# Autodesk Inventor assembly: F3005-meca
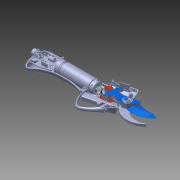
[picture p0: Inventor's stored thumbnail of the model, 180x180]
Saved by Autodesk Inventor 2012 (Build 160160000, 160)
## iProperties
Created: 2014-12
Part Number: F3005-meca
Document SubType Name: Assembly
Designer: Bruno
Author: Bruno
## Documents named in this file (6)
- F:\Systèmes\secateur-hydrogene-Pragma\Documentation\Dossier technique Infaco F3005\Solidworks\Composants importés\F3005-meca.iam
- F:\Systèmes\secateur-hydrogene-Pragma\Documentation\Dossier technique Infaco F3005\Solidworks\Composants importés\F3005-bati.iam
- F:\Systèmes\secateur-hydrogene-Pragma\Documentation\Dossier technique Infaco F3005\Solidworks\Composants importés\F3005\Gachette.ipt
- F:\Systèmes\secateur-hydrogene-Pragma\Documentation\Dossier technique Infaco F3005\Solidworks\Composants importés\F3005-lame-mobile.iam
- F:\Systèmes\secateur-hydrogene-Pragma\Documentation\Dossier technique Infaco F3005\Solidworks\Composants importés\F3005--pignon-intermédiaire.iam
- F:\Systèmes\secateur-hydrogene-Pragma\Documentation\Dossier technique Infaco F3005\Solidworks\Composants importés\F3005-arbre-moteur.iam
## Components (5 placed, 5 different names)
1. F3005-bati:1 [sub-assembly] — Placage:1, Placage:2, Logement:1, Placage:3, Placage:4, Placage:5, Placage:6
2. Gachette:1 — Placage:1, Placage:2
3. F3005-lame-mobile:1 [sub-assembly] — Logement:1
4. F3005--pignon-intermédiaire:1 [sub-assembly] — Placage:3, Placage:4
5. F3005-arbre-moteur:1 [sub-assembly] — Placage:5, Placage:6
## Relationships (7: Mate 6, Insert 1)
- Placage:1 [Mate]: F3005-bati:1 ↔ Gachette:1
- Placage:2 [Mate]: F3005-bati:1 ↔ Gachette:1
- Logement:1 [Insert]: F3005-bati:1 ↔ F3005-lame-mobile:1
- Placage:3 [Mate]: F3005-bati:1 ↔ F3005--pignon-intermédiaire:1
- Placage:4 [Mate]: F3005-bati:1 ↔ F3005--pignon-intermédiaire:1
- Placage:5 [Mate]: F3005-bati:1 ↔ F3005-arbre-moteur:1
- Placage:6 [Mate]: F3005-bati:1 ↔ F3005-arbre-moteur:1
